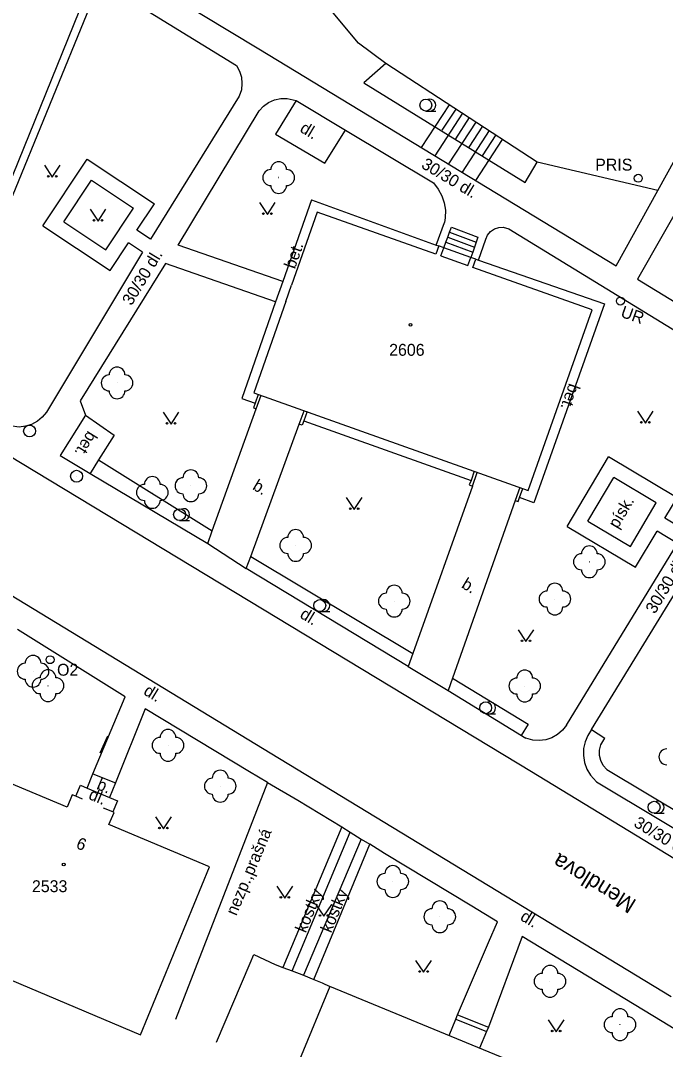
# Model space of a CAD drawing. Extents: x -584400 to -581602, y -1210894 to -1208793.
# Drawn here: x -582520.8 to -582480.2, y -1210012 to -1209947.1 of the extents above; entities that cross this region are included whole.
import ezdxf

# ---------------------------------------------------------------- set-up
doc = ezdxf.new("R2010")
doc.units = 0
for name, color, linetype in [('BUDOVY_MĚŘ', 7, 'Continuous'), ('MAP_ZN_BP', 7, 'Continuous'), ('NÁZVY_ULIC_TOK_SMĚR', 7, 'Continuous'), ('POMOC_POPIS', 7, 'Continuous'), ('ROZHRANÍ_PLOCH', 7, 'Continuous'), ('VÝŠKOPIS', 7, 'Continuous'), ('ZELEŇ', 7, 'Continuous'), ('ZN_BUDOV', 7, 'Continuous'), ('ZN_DOPLŇKOVÉ', 7, 'Continuous'), ('ZN_KULTUR', 7, 'Continuous'), ('Č_POPIS_EVID', 7, 'Continuous')]:
    doc.layers.add(name, color=color, linetype=linetype)

msp = doc.modelspace()

# ---------------------------------------------------------------- linework, layer by layer
at = {"layer": 'BUDOVY_MĚŘ'}
for points in [[(-582517.17, -1209946.58), (-582521.68, -1209957.72)], [(-582494.18, -1209961.44), (-582494.49, -1209961.33), (-582494.68, -1209961.85), (-582502.15, -1209959.19), (-582503.78, -1209963.8)], [(-582494.36, -1209961.96), (-582494.18, -1209961.44)], [(-582494.36, -1209961.96), (-582492.66, -1209962.57), (-582492.47, -1209962.06)], [(-582492.47, -1209962.06), (-582494.18, -1209961.44)], [(-582504.12, -1209964.83), (-582506.15, -1209970.58), (-582488.87, -1209976.74), (-582484.83, -1209965.35), (-582492.35, -1209962.68), (-582492.16, -1209962.17), (-582492.47, -1209962.06)], [(-582516.94, -1209996.19), (-582517.36, -1209996.01), (-582517.59, -1209995.92), (-582517.91, -1209996.69), (-582524.19, -1209994.06), (-582528.53, -1210004.6), (-582513.29, -1210011.04), (-582508.93, -1210000.46), (-582515.28, -1209997.79), (-582514.95, -1209997.02), (-582515.02, -1209996.99), (-582515.61, -1209996.75)], [(-582486.31, -1210019.62), (-582484.4, -1210015), (-582501.36, -1210007.99), (-582503.27, -1210012.61)]]:
    msp.add_lwpolyline(points, dxfattribs=at)
at = {"layer": 'MAP_ZN_BP'}
for centre, radius in [((-582520.27, -1209972.99), 0.375), ((-582520.27, -1209972.99), 0.0005), ((-582517.31, -1209975.841), 0.375), ((-582517.31, -1209975.841), 0.0005)]:
    msp.add_circle(centre, radius, dxfattribs=at)
at = {"layer": 'ROZHRANÍ_PLOCH'}
for points in [[(-582480.69, -1209957.83), (-582475.89, -1209949.13), (-582475.61, -1209947.19), (-582479.16, -1209938), (-582506.68, -1209937.89), (-582506.72, -1209927.01), (-582507.45, -1209926.2), (-582528.2, -1209925.75), (-582529.35, -1209927.61)], [(-582529.35, -1209927.61), (-582532.41, -1209932.87), (-582505.82, -1209948.9), (-582483.32, -1209962.59), (-582480.69, -1209957.83)], [(-582516.48, -1209946.23), (-582516.64, -1209944.16), (-582507.23, -1209949.95), (-582507.04, -1209950.31), (-582506.93, -1209950.69), (-582506.89, -1209951.09), (-582506.93, -1209951.49), (-582507.06, -1209951.89), (-582512.66, -1209960.9), (-582513.51, -1209960.34), (-582512.4, -1209958.67)], [(-582516.48, -1209946.23), (-582521.56, -1209958.68)], [(-582504.32, -1209963.57), (-582510.92, -1209961.28), (-582505.81, -1209952.82), (-582505.54, -1209952.53), (-582505.21, -1209952.29), (-582504.84, -1209952.13), (-582504.45, -1209952.04), (-582504.04, -1209952.03), (-582503.48, -1209952.16)], [(-582503.48, -1209952.16), (-582504.78, -1209954.28), (-582501.68, -1209956.11), (-582500.36, -1209954.04)], [(-582503.48, -1209952.16), (-582500.36, -1209954.04)], [(-582500.36, -1209954.04), (-582494.82, -1209957.36), (-582494.53, -1209957.74), (-582494.3, -1209958.16), (-582494.15, -1209958.61), (-582494.08, -1209959.08), (-582494.09, -1209959.56), (-582494.13, -1209959.84)], [(-582519.44, -1209960.07), (-582516.65, -1209955.86), (-582512.4, -1209958.67)], [(-582518.12, -1209959.8), (-582516.38, -1209957.18), (-582513.72, -1209958.94)], [(-582478.65, -1209957.6), (-582481.97, -1209963.43), (-582479.6, -1209964.88)], [(-582502.52, -1209958.43), (-582504.32, -1209963.57)], [(-582502.52, -1209958.43), (-582494.65, -1209961.27)], [(-582518.12, -1209959.8), (-582515.46, -1209961.57), (-582513.72, -1209958.94)], [(-582546.53, -1209959.45), (-582528.79, -1209970.19), (-582488.65, -1209994.44), (-582474.47, -1210003.08)], [(-582494.65, -1209961.27), (-582494.13, -1209959.84)], [(-582519.44, -1209960.07), (-582515.19, -1209962.88), (-582514.03, -1209961.13)], [(-582491.99, -1209962.23), (-582491.53, -1209960.91), (-582491.42, -1209960.65), (-582491.23, -1209960.42), (-582490.99, -1209960.26), (-582490.72, -1209960.17), (-582490.43, -1209960.15), (-582490.09, -1209960.24), (-582475.02, -1209969.47), (-582474.74, -1209969.75), (-582474.51, -1209970.08), (-582474.36, -1209970.45), (-582474.28, -1209970.85), (-582474.28, -1209971.25), (-582474.36, -1209971.64), (-582474.45, -1209971.88)], [(-582513.16, -1209961.71), (-582514.03, -1209961.13)], [(-582494.65, -1209961.27), (-582494.49, -1209961.33)], [(-582513.16, -1209961.71), (-582519.21, -1209971.8), (-582519.47, -1209972.12), (-582519.78, -1209972.38), (-582520.14, -1209972.57), (-582520.52, -1209972.69), (-582520.93, -1209972.74), (-582521.49, -1209972.66), (-582526.25, -1209969.76), (-582526.91, -1209969.37)], [(-582504.77, -1209964.85), (-582511.71, -1209962.44), (-582517.09, -1209971.09), (-582516.75, -1209971.99)], [(-582492.16, -1209962.17), (-582491.99, -1209962.23)], [(-582491.99, -1209962.23), (-582484.06, -1209964.98), (-582488.5, -1209977.51), (-582489.4, -1209977.19)], [(-582504.32, -1209963.57), (-582504.77, -1209964.85)], [(-582504.77, -1209964.85), (-582506.91, -1209970.94), (-582506.07, -1209971.24)], [(-582509.05, -1209980.07), (-582508.77, -1209979.29), (-582505.99, -1209971.59)], [(-582516.75, -1209971.99), (-582518.34, -1209974.54), (-582516.45, -1209975.67)], [(-582516.75, -1209971.99), (-582514.95, -1209973.26), (-582515.92, -1209974.81), (-582516.45, -1209975.67)], [(-582503, -1209972.34), (-582492.46, -1209976.1)], [(-582506.62, -1209981.65), (-582506.34, -1209980.89), (-582503.28, -1209972.55)], [(-582486.41, -1209979), (-582483.8, -1209974.62)], [(-582478.95, -1209979.26), (-582480.25, -1209978.48), (-582479.48, -1209977.2), (-582483.8, -1209974.62)], [(-582516.45, -1209975.67), (-582509.05, -1209980.07)], [(-582485.11, -1209978.67), (-582483.47, -1209975.93)], [(-582485.11, -1209978.67), (-582482.42, -1209980.27), (-582480.79, -1209977.52), (-582483.47, -1209975.93)], [(-582533.05, -1209976.28), (-582505.59, -1209992.98), (-582479.86, -1210008.62)], [(-582492.38, -1209976.46), (-582496.13, -1209987), (-582496.43, -1209987.83)], [(-582492.57, -1209976.39), (-582492.38, -1209976.46)], [(-582489.68, -1209977.36), (-582493.63, -1209988.57), (-582493.9, -1209989.35)], [(-582486.44, -1209991.53), (-582479.45, -1209980.07), (-582480.74, -1209979.3)], [(-582486.41, -1209979), (-582482.1, -1209981.58), (-582480.74, -1209979.3)], [(-582509.05, -1209980.07), (-582506.62, -1209981.65)], [(-582496.43, -1209987.83), (-582506.62, -1209981.65)], [(-582484.87, -1209991.8), (-582478.84, -1209981.96)], [(-582516.28, -1209994.6), (-582514.24, -1209989.75), (-582521.03, -1209985.5)], [(-582496.43, -1209987.83), (-582493.9, -1209989.35)], [(-582493.9, -1209989.35), (-582489.01, -1209992.35)], [(-582505.28, -1209995.14), (-582506.42, -1209994.47), (-582512.99, -1209990.5), (-582514.85, -1209995.17)], [(-582486.44, -1209991.53), (-582486.7, -1209991.85), (-582487.01, -1209992.12), (-582487.37, -1209992.32), (-582487.76, -1209992.45), (-582488.16, -1209992.5), (-582488.57, -1209992.47), (-582489.01, -1209992.35)], [(-582484.87, -1209991.8), (-582485.11, -1209992.17), (-582485.28, -1209992.57), (-582485.37, -1209993), (-582485.38, -1209993.44), (-582485.31, -1209993.87), (-582485.16, -1209994.29), (-582484.94, -1209994.67), (-582484.55, -1209995.1), (-582476.61, -1209999.87)], [(-582516.65, -1209995.49), (-582516.28, -1209994.6)], [(-582516.28, -1209994.6), (-582514.85, -1209995.17)], [(-582517.36, -1209996.01), (-582517.07, -1209995.31), (-582516.65, -1209995.49)], [(-582516.65, -1209995.49), (-582515.23, -1209996.08)], [(-582514.85, -1209995.17), (-582515.23, -1209996.08)], [(-582505.28, -1209995.14), (-582508.05, -1210002.29), (-582511.07, -1210010.08)], [(-582505.28, -1209995.14), (-582503.38, -1209996.26)], [(-582515.23, -1209996.08), (-582514.73, -1209996.29), (-582515.02, -1209996.99)], [(-582503.38, -1209996.26), (-582500.61, -1209997.94)], [(-582500.61, -1209997.94), (-582504.32, -1210006.79)], [(-582503.72, -1210007), (-582500.07, -1209998.26)], [(-582500.61, -1209997.94), (-582500.07, -1209998.26)], [(-582500.07, -1209998.26), (-582499.38, -1209998.7)], [(-582499.38, -1209998.7), (-582503.01, -1210007.29)], [(-582499.38, -1209998.7), (-582498.83, -1209999.02)], [(-582502.37, -1210007.55), (-582498.83, -1209999.02)], [(-582493.31, -1210009.77), (-582491.36, -1210005.23), (-582490.79, -1210003.92), (-582492.42, -1210002.93), (-582497.91, -1209999.62), (-582498.83, -1209999.02)], [(-582480.43, -1210010.21), (-582489.24, -1210004.85), (-582491.36, -1210010.55)], [(-582476.44, -1210012.64), (-582480.43, -1210010.21)]]:
    msp.add_lwpolyline(points, dxfattribs=at)
at = {"layer": 'VÝŠKOPIS'}
for points in [[(-582480.69, -1209957.83), (-582488.29, -1209956.04), (-582497.83, -1209949.84), (-582499.55, -1209948.54), (-582506.64, -1209940.02), (-582511.49, -1209932.74), (-582523.21, -1209929.98), (-582529.35, -1209927.61)], [(-582493.85, -1209952.43), (-582495.6, -1209955.12)], [(-582493.43, -1209952.7), (-582494.3, -1209954.04)], [(-582493.01, -1209952.97), (-582494.74, -1209955.64)], [(-582492.17, -1209953.52), (-582493.89, -1209956.16)], [(-582492.59, -1209953.24), (-582493.45, -1209954.57)], [(-582491.33, -1209954.06), (-582493.03, -1209956.68)], [(-582491.75, -1209953.79), (-582492.61, -1209955.1)], [(-582490.5, -1209954.61), (-582492.18, -1209957.2)], [(-582490.91, -1209954.33), (-582491.76, -1209955.64)]]:
    msp.add_lwpolyline(points, dxfattribs=at)
at = {"layer": 'ZELEŇ'}
for points in [[(-582497.83, -1209949.84), (-582499.22, -1209951.05), (-582489.06, -1209957.32), (-582488.29, -1209956.04)], [(-582515.92, -1209974.81), (-582508.77, -1209979.29)], [(-582506.34, -1209980.89), (-582496.13, -1209987)], [(-582493.63, -1209988.57), (-582488.87, -1209991.46), (-582489.31, -1209992.17)], [(-582484.87, -1209991.8), (-582484.03, -1209992.34)], [(-582483.91, -1209994.32), (-582484.13, -1209994.07), (-582484.28, -1209993.76), (-582484.36, -1209993.43), (-582484.36, -1209993.1), (-582484.28, -1209992.77), (-582484.03, -1209992.34)], [(-582483.91, -1209994.32), (-582476.23, -1209998.93)]]:
    msp.add_lwpolyline(points, dxfattribs=at)
for centre in [(-582504.58, -1209957.02), (-582514.76, -1209969.96), (-582512.54, -1209976.86), (-582510.11, -1209976.44), (-582503.51, -1209980.2), (-582485.01, -1209981.23), (-582497.3, -1209983.71), (-582487.18, -1209983.58), (-582520.05, -1209988.13), (-582519.11, -1209989.04), (-582489.08, -1209989.06), (-582511.55, -1209992.8), (-582508.26, -1209995.37), (-582497.39, -1210001.38), (-582494.43, -1210003.6), (-582487.49, -1210007.67), (-582483.08, -1210010.4)]:
    msp.add_circle(centre, 0.0005, dxfattribs=at)
for centre, start, end in [((-582504.58, -1209956.52), 0, 179.99999), ((-582505.08, -1209957.02), 89.99999, 269.99999), ((-582504.08, -1209957.02), 270, 89.99999), ((-582504.58, -1209957.52), 179.99999, 359.99999), ((-582514.76, -1209969.46), 0, 179.99999), ((-582515.26, -1209969.96), 89.99999, 269.99999), ((-582514.26, -1209969.96), 270, 89.99999), ((-582514.76, -1209970.46), 179.99999, 359.99999), ((-582510.11, -1209975.94), 0, 179.99999), ((-582512.54, -1209976.36), 0, 179.99999), ((-582510.61, -1209976.44), 89.99999, 269.99999), ((-582509.61, -1209976.44), 270, 89.99999), ((-582513.04, -1209976.86), 89.99999, 269.99999), ((-582512.04, -1209976.86), 270, 89.99999), ((-582512.54, -1209977.36), 179.99999, 359.99999), ((-582510.11, -1209976.94), 179.99999, 359.99999), ((-582503.51, -1209979.7), 0, 179.99999), ((-582504.01, -1209980.2), 89.99999, 269.99999), ((-582503.01, -1209980.2), 270, 89.99999), ((-582503.51, -1209980.7), 179.99999, 359.99999), ((-582485.51, -1209981.23), 89.99999, 269.99999), ((-582485.01, -1209980.73), 0, 179.99999), ((-582484.51, -1209981.23), 270, 89.99999), ((-582485.01, -1209981.73), 179.99999, 359.99999), ((-582497.3, -1209983.21), 0, 179.99999), ((-582487.18, -1209983.08), 0, 179.99999), ((-582497.8, -1209983.71), 89.99999, 269.99999), ((-582496.8, -1209983.71), 270, 89.99999), ((-582487.68, -1209983.58), 89.99999, 269.99999), ((-582486.68, -1209983.58), 270, 89.99999), ((-582497.3, -1209984.21), 179.99999, 359.99999), ((-582487.18, -1209984.08), 179.99999, 359.99999), ((-582520.05, -1209987.63), 0, 179.99999), ((-582520.55, -1209988.13), 89.99999, 269.99999), ((-582519.55, -1209988.13), 270, 89.99999), ((-582519.61, -1209989.04), 89.99999, 269.99999), ((-582519.11, -1209988.54), 0, 179.99999), ((-582518.61, -1209989.04), 270, 89.99999), ((-582489.58, -1209989.06), 89.99999, 269.99999), ((-582489.08, -1209988.56), 0, 179.99999), ((-582488.58, -1209989.06), 270, 89.99999), ((-582520.05, -1209988.63), 179.99999, 359.99999), ((-582519.11, -1209989.54), 179.99999, 359.99999), ((-582489.08, -1209989.56), 179.99999, 359.99999), ((-582511.55, -1209992.3), 0, 179.99999), ((-582512.05, -1209992.8), 89.99999, 269.99999), ((-582511.05, -1209992.8), 270, 89.99999), ((-582480.13, -1209993.52), 89.99999, 269.99999), ((-582511.55, -1209993.3), 179.99999, 359.99999), ((-582508.26, -1209994.87), 0, 179.99999), ((-582508.76, -1209995.37), 89.99999, 269.99999), ((-582507.76, -1209995.37), 270, 89.99999), ((-582508.26, -1209995.87), 179.99999, 359.99999), ((-582497.89, -1210001.38), 89.99999, 269.99999), ((-582497.39, -1210000.88), 0, 179.99999), ((-582496.89, -1210001.38), 270, 89.99999), ((-582497.39, -1210001.88), 179.99999, 359.99999), ((-582494.43, -1210003.1), 0, 179.99999), ((-582494.93, -1210003.6), 89.99999, 269.99999), ((-582493.93, -1210003.6), 270, 89.99999), ((-582494.43, -1210004.1), 179.99999, 359.99999), ((-582487.49, -1210007.17), 0, 179.99999), ((-582487.99, -1210007.67), 89.99999, 269.99999), ((-582486.99, -1210007.67), 270, 89.99999), ((-582487.49, -1210008.17), 179.99999, 359.99999), ((-582483.58, -1210010.4), 89.99999, 269.99999), ((-582483.08, -1210009.9), 0, 179.99999), ((-582482.58, -1210010.4), 270, 89.99999), ((-582483.08, -1210010.9), 179.99999, 359.99999)]:
    msp.add_arc(centre, 0.5, start, end, dxfattribs=at)
at = {"layer": 'ZN_BUDOV'}
for centre in [(-582496.27, -1209966.3), (-582518.12, -1210000.31)]:
    msp.add_circle(centre, 0.0875, dxfattribs=at)
at = {"layer": 'ZN_DOPLŇKOVÉ'}
for points in [[(-582493.93, -1209960.77), (-582493.81, -1209960.46)], [(-582493.81, -1209960.46), (-582493.7, -1209960.15), (-582492.03, -1209960.78), (-582492.14, -1209961.09)], [(-582493.81, -1209960.46), (-582492.14, -1209961.09)], [(-582494.18, -1209961.44), (-582494.04, -1209961.08)], [(-582494.04, -1209961.08), (-582493.93, -1209960.77)], [(-582494.04, -1209961.08), (-582492.35, -1209961.71)], [(-582493.93, -1209960.77), (-582492.24, -1209961.4)], [(-582492.14, -1209961.09), (-582492.24, -1209961.4)], [(-582492.35, -1209961.71), (-582492.47, -1209962.06)], [(-582492.24, -1209961.4), (-582492.35, -1209961.71)], [(-582504.12, -1209964.83), (-582503.78, -1209963.8)], [(-582505.87, -1209970.68), (-582506.07, -1209971.24), (-582506.17, -1209971.53), (-582505.99, -1209971.59), (-582505.68, -1209970.74)], [(-582502.79, -1209971.77), (-582503, -1209972.34), (-582503.1, -1209972.62), (-582503.28, -1209972.55), (-582502.98, -1209971.71)], [(-582492.26, -1209975.53), (-582492.46, -1209976.1), (-582492.57, -1209976.39)], [(-582492.38, -1209976.46), (-582492.07, -1209975.6)], [(-582489.39, -1209976.56), (-582489.68, -1209977.36), (-582489.49, -1209977.43), (-582489.4, -1209977.19), (-582489.2, -1209976.62)], [(-582515.36, -1209992.21), (-582515.85, -1209993.3)], [(-582506.37, -1210006.52), (-582506.14, -1210005.98), (-582504.79, -1210006.6)], [(-582508.49, -1210011.51), (-582506.37, -1210006.52)], [(-582504.79, -1210006.6), (-582504.32, -1210006.79)], [(-582504.32, -1210006.79), (-582503.72, -1210007)], [(-582503.72, -1210007), (-582503.01, -1210007.29)], [(-582503.01, -1210007.29), (-582502.37, -1210007.55)], [(-582502.37, -1210007.55), (-582501.85, -1210007.77)], [(-582501.85, -1210007.77), (-582501.36, -1210007.99)], [(-582493.42, -1210010.05), (-582493.31, -1210009.77), (-582491.36, -1210010.55), (-582491.48, -1210010.83)], [(-582493.85, -1210011.09), (-582493.42, -1210010.05)], [(-582493.42, -1210010.05), (-582491.48, -1210010.83)], [(-582491.48, -1210010.83), (-582491.92, -1210011.89)]]:
    msp.add_lwpolyline(points, dxfattribs=at)
for centre, radius in [((-582481.931, -1209957.06), 0.25), ((-582481.931, -1209957.06), 0.0005), ((-582483.051, -1209964.8), 0.25), ((-582483.051, -1209964.8), 0.0005), ((-582518.981, -1209987.4), 0.25), ((-582518.981, -1209987.4), 0.0005)]:
    msp.add_circle(centre, radius, dxfattribs=at)
at = {"layer": 'ZN_KULTUR'}
for p, q in [((-582495.31, -1209952.825), (-582494.685, -1209952.825)), ((-582510.82, -1209978.635), (-582510.195, -1209978.635)), ((-582501.99, -1209984.365), (-582501.365, -1209984.365)), ((-582491.54, -1209990.805), (-582490.915, -1209990.805)), ((-582480.93, -1209997.075), (-582480.305, -1209997.075))]:
    msp.add_line(p, q, dxfattribs=at)
for points in [[(-582519.34, -1209956.24), (-582518.84, -1209956.99), (-582518.34, -1209956.24)], [(-582505.79, -1209958.59), (-582505.29, -1209959.34), (-582504.79, -1209958.59)], [(-582516.46, -1209959.01), (-582515.96, -1209959.76), (-582515.46, -1209959.01)], [(-582511.86, -1209971.8), (-582511.36, -1209972.55), (-582510.86, -1209971.8)], [(-582481.98, -1209971.74), (-582481.48, -1209972.49), (-582480.98, -1209971.74)], [(-582500.32, -1209977.19), (-582499.82, -1209977.94), (-582499.32, -1209977.19)], [(-582489.5, -1209985.51), (-582489, -1209986.26), (-582488.5, -1209985.51)], [(-582512.34, -1209997.31), (-582511.84, -1209998.06), (-582511.34, -1209997.31)], [(-582504.69, -1210001.68), (-582504.19, -1210002.43), (-582503.69, -1210001.68)], [(-582502.23, -1210002.82), (-582501.73, -1210003.57), (-582501.23, -1210002.82)], [(-582495.95, -1210006.35), (-582495.45, -1210007.1), (-582494.95, -1210006.35)], [(-582487.6, -1210010.1), (-582487.1, -1210010.85), (-582486.6, -1210010.1)]]:
    msp.add_lwpolyline(points, dxfattribs=at)
for centre, radius in [((-582495.31, -1209952.45), 0.375), ((-582519.09, -1209956.94), 0.05), ((-582518.59, -1209956.94), 0.05), ((-582505.54, -1209959.29), 0.05), ((-582505.04, -1209959.29), 0.05), ((-582516.21, -1209959.71), 0.05), ((-582515.71, -1209959.71), 0.05), ((-582511.61, -1209972.5), 0.05), ((-582511.11, -1209972.5), 0.05), ((-582481.73, -1209972.44), 0.05), ((-582481.23, -1209972.44), 0.05), ((-582510.82, -1209978.26), 0.375), ((-582500.07, -1209977.89), 0.05), ((-582499.57, -1209977.89), 0.05), ((-582501.99, -1209983.99), 0.375), ((-582489.25, -1209986.21), 0.05), ((-582488.75, -1209986.21), 0.05), ((-582491.54, -1209990.43), 0.375), ((-582480.93, -1209996.7), 0.375), ((-582512.09, -1209998.01), 0.05), ((-582511.59, -1209998.01), 0.05), ((-582504.44, -1210002.38), 0.05), ((-582503.94, -1210002.38), 0.05), ((-582501.98, -1210003.52), 0.05), ((-582501.48, -1210003.52), 0.05), ((-582495.7, -1210007.05), 0.05), ((-582495.2, -1210007.05), 0.05), ((-582487.35, -1210010.8), 0.05), ((-582486.85, -1210010.8), 0.05)]:
    msp.add_circle(centre, radius, dxfattribs=at)
for centre in [(-582495.06, -1209952.45), (-582510.57, -1209978.26), (-582501.74, -1209983.99), (-582491.29, -1209990.43), (-582480.68, -1209996.7)]:
    msp.add_arc(centre, 0.375, 249.49437, 109.04743, dxfattribs=at)

# ---------------------------------------------------------------- texts
at = {"layer": 'NÁZVY_ULIC_TOK_SMĚR'}
msp.add_text('Mendlova', height=1, rotation=148.38364, dxfattribs=at).set_placement((-582481.98, -1210002.59))
at = {"layer": 'POMOC_POPIS'}
for s, rotation, p in [('dl.', 329.13635, (-582503.3, -1209954.1)), ('30/30 dl.', 328.92837, (-582495.65, -1209956.37)), ('bet.', 70.52749, (-582503.56, -1209962.82)), ('30/30 dl.', 58.86723, (-582513.85, -1209965.13)), ('UR', 340.45439, (-582483.09, -1209965.78)), ('bet.', 250.47056, (-582486.28, -1209969.94)), ('bet.', 238.05525, (-582516.59, -1209972.93)), ('b.', 328.76811, (-582506.28, -1209976.63)), ('písk.', 59.34365, (-582483.23, -1209979.19)), ('30/30 dl.', 59.18431, (-582480.88, -1209984.56)), ('b.', 328.76811, (-582493.12, -1209982.83)), ('dl.', 328.76811, (-582503.3, -1209984.72)), ('dl.', 328.55337, (-582513.15, -1209989.55)), ('b.', 337.27653, (-582516.1, -1209995.53)), ('dl.', 337.16635, (-582516.61, -1209996.16)), ('30/30 dl.', 329.03625, (-582482.27, -1209997.87)), ('nezp.,prašná', 67.27493, (-582507.25, -1210003.58)), ('kostky', 67.3336, (-582502.88, -1210004.66)), ('kostky', 67.46125, (-582501.28, -1210004.66)), ('dl.', 328.55337, (-582489.42, -1210003.77))]:
    msp.add_text(s, height=0.75, rotation=rotation, dxfattribs=at).set_placement(p)
for s, p in [('PRIS', (-582484.64, -1209956.58)), ('O2', (-582518.54, -1209988.41))]:
    msp.add_text(s, height=0.75, dxfattribs=at).set_placement(p)
at = {"layer": 'Č_POPIS_EVID'}
for s, p in [('2606', (-582497.62, -1209968.25)), ('2533', (-582520.12, -1210002.05))]:
    msp.add_text(s, height=0.75, dxfattribs=at).set_placement(p)
msp.add_text('6', height=0.75, rotation=337.25499, dxfattribs=at).set_placement((-582517.4, -1209999.25))

doc.saveas('drawing.dxf')
